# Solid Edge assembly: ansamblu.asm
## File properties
Author: Ionut
Template: Normal.asm
Last saved by: user
Revision: 12
Application: Solid Edge
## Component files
cadru.par
cupla.par
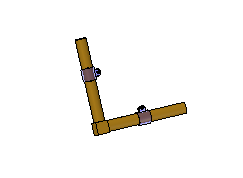
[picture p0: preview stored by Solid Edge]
